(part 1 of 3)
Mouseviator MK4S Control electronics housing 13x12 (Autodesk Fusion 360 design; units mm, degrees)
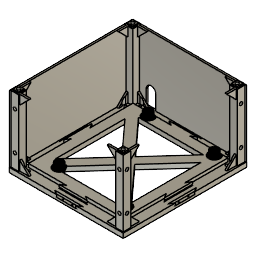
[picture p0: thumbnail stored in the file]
parameter "plate_width" = 130
parameter "plate_height" = 120
parameter "join_width1" = 10
parameter "join_width2" = 15
parameter "join_depth" = 3
parameter "plate_thick" = 5
parameter "plate_mount_square_side" = 7
parameter "locke_handle_height_1" = 8
parameter "lock_handle_chamfer_1" = 5
parameter "lock_handle_fillet_1" = 0.5
parameter "column_height" = 70
parameter "support_column_side" = 8
parameter "top_cover_thickness" = 3
parameter "wall_clearance" = 0.05
parameter "print_layer_height" = 0.2
parameter "side_wall_thick1" = 0.95 (= "( ( plate_square_thick - support_column_side ) / 2 ) - wall_clearance")
parameter "side_wall_thick2" = 1.95 (= "plate_square_thick - support_column_side - wall_clearance")
parameter "side_wall_length_L_inner" = 111.9 (= "plate_width - ( side_wall_col_length * 2 )")
parameter "side_wall_length_S_inner" = 101.9 (= "plate_height - ( side_wall_col_length * 2 )")
parameter "join_key_d" = 1.5 (= "join_depth / 2")
parameter "join_key_distance" = 5 (= "join_width1 / 2")
parameter "locke_handle_height_2" = 8
parameter "lock_handle_chamfer_2" = 5
parameter "lock_handle_fillet_2" = 0.5
parameter "locke_handle_height_3" = 8
parameter "lock_handle_chamfer_3" = 5
parameter "lock_handle_fillet_3" = 0.5
parameter "lock_column_clearance" = 0.075 (= "wall_clearance * 1.5")
parameter "psu_width" = 99
parameter "psu_height" = 82.5
parameter "psu_stand_height" = 5
parameter "joiner_spacing_1" = -0.05
parameter "joiner_spacing_2" = -0.05
parameter "joiner_spacing_2_1" = -0.05
parameter "joiner_spacing_2_2" = -0.05
parameter "joiner_spacing_3_1" = -0.05
parameter "plate_square_thick_1" = 10
parameter "column_lock_spacing_1" = 2
sketch "Sketch1" plane through (0, 0, 0) normal (0, 0, 1) x axis (1, 0, 0)
  line L1 (130.9644, 61.9879) -> (10.9644, 61.9879)
  line L2 (130.9644, -68.0121) -> (130.9644, 61.9879)
  line L3 (10.9644, -68.0121) -> (130.9644, -68.0121)
  line L4 (10.9644, 61.9879) -> (10.9644, -68.0121)
  line L5 (70.9644, -84.5025) -> (70.9644, 72)
  line L6 (146.0369, -3.0121) -> (3.7538, -3.0121)
  line L7 (120.9644, 51.9879) -> (20.9644, 51.9879)
  line L8 (120.9644, -58.0121) -> (120.9644, 51.9879)
  line L9 (20.9644, -58.0121) -> (120.9644, -58.0121)
  line L10 (20.9644, 51.9879) -> (20.9644, -58.0121)
  line L11 (20.9644, 61.9879) -> (10.9644, 61.9879)
  line L12 (20.9644, 51.9879) -> (20.9644, 61.9879)
  line L13 (10.9644, 51.9879) -> (20.9644, 51.9879)
  line L14 (10.9644, 61.9879) -> (10.9644, 51.9879)
  line L15 (120.9644, 61.9879) -> (130.9644, 61.9879)
  line L16 (120.9644, 51.9879) -> (120.9644, 61.9879)
  line L17 (130.9644, 51.9879) -> (120.9644, 51.9879)
  line L18 (130.9644, 61.9879) -> (130.9644, 51.9879)
  line L19 (120.9644, -68.0121) -> (130.9644, -68.0121)
  line L20 (120.9644, -58.0121) -> (120.9644, -68.0121)
  line L21 (130.9644, -58.0121) -> (120.9644, -58.0121)
  line L22 (130.9644, -68.0121) -> (130.9644, -58.0121)
  line L23 (20.9644, -68.0121) -> (10.9644, -68.0121)
  line L24 (20.9644, -58.0121) -> (20.9644, -68.0121)
  line L25 (10.9644, -58.0121) -> (20.9644, -58.0121)
  line L26 (10.9644, -68.0121) -> (10.9644, -58.0121)
  line L27 (122.9644, 59.9879) -> (128.9644, 59.9879)
  line L28 (122.9644, 53.9879) -> (122.9644, 59.9879)
  line L29 (128.9644, 53.9879) -> (122.9644, 53.9879)
  line L30 (128.9644, 59.9879) -> (128.9644, 53.9879)
  line L31 (18.9644, -66.0121) -> (12.9644, -66.0121)
  line L32 (18.9644, -60.0121) -> (18.9644, -66.0121)
  line L33 (12.9644, -60.0121) -> (18.9644, -60.0121)
  line L34 (12.9644, -66.0121) -> (12.9644, -60.0121)
  line L35 (18.9644, 59.9879) -> (12.9644, 59.9879)
  line L36 (18.9644, 53.9879) -> (18.9644, 59.9879)
  line L37 (12.9644, 53.9879) -> (18.9644, 53.9879)
  line L38 (12.9644, 59.9879) -> (12.9644, 53.9879)
  line L39 (122.9644, -66.0121) -> (128.9644, -66.0121)
  line L40 (122.9644, -60.0121) -> (122.9644, -66.0121)
  line L41 (128.9644, -60.0121) -> (122.9644, -60.0121)
  line L42 (128.9644, -66.0121) -> (128.9644, -60.0121)
  line L43 (60.9644, 51.9879) -> (70.9644, 51.9879)
  line L44 (80.9644, 51.9879) -> (70.9644, 51.9879)
  line L45 (70.9644, 54.9879) -> (70.9644, 51.9879)
  line L46 (85.9644, 54.9879) -> (70.9644, 54.9879)
  line L47 (55.9644, 54.9879) -> (70.9644, 54.9879)
  line L48 (55.9644, 54.9879) -> (60.9644, 51.9879)
  line L49 (80.9644, 51.9879) -> (85.9644, 54.9879)
  line L50 (111.4916, 56.9879) -> (2, 56.9879)
  line L51 (55.9644, 58.9879) -> (70.9644, 58.9879)
  line L52 (55.9644, 58.9879) -> (60.9644, 61.9879)
  line L53 (60.9644, 61.9879) -> (70.9644, 61.9879)
  line L54 (80.9644, 61.9879) -> (85.9644, 58.9879)
  line L55 (80.9644, 61.9879) -> (70.9644, 61.9879)
  line L56 (85.9644, 58.9879) -> (70.9644, 58.9879)
  line L57 (85.9644, -61.0121) -> (70.9644, -61.0121)
  line L58 (80.9644, -58.0121) -> (85.9644, -61.0121)
  line L59 (80.9644, -58.0121) -> (70.9644, -58.0121)
  line L60 (55.9644, -61.0121) -> (60.9644, -58.0121)
  line L61 (60.9644, -58.0121) -> (70.9644, -58.0121)
  line L62 (55.9644, -61.0121) -> (70.9644, -61.0121)
  line L63 (55.9644, -65.0121) -> (60.9644, -68.0121)
  line L64 (60.9644, -68.0121) -> (70.9644, -68.0121)
  line L65 (80.9644, -68.0121) -> (70.9644, -68.0121)
  line L66 (80.9644, -68.0121) -> (85.9644, -65.0121)
  line L67 (85.9644, -65.0121) -> (70.9644, -65.0121)
  line L68 (55.9644, -65.0121) -> (70.9644, -65.0121)
  line L69 (60.9644, 51.9879) -> (20.9644, 51.9879)
  line L70 (80.9644, 51.9879) -> (120.9644, 51.9879)
  line L71 (80.9644, -58.0121) -> (120.9644, -58.0121)
  line L72 (60.9644, -58.0121) -> (20.9644, -58.0121)
  line L73 (125.9644, -76) -> (125.9644, 65)
  line L74 (120.9644, 6.9879) -> (120.9644, -3.0121)
  line L75 (120.9644, -13.0121) -> (120.9644, -3.0121)
  line L76 (123.9644, -3.0121) -> (120.9644, -3.0121)
  line L77 (123.9644, 11.9879) -> (123.9644, -3.0121)
  line L78 (123.9644, -18.0121) -> (123.9644, -3.0121)
  line L79 (123.9644, 11.9879) -> (120.9644, 6.9879)
  line L80 (123.9644, -18.0121) -> (120.9644, -13.0121)
  line L81 (127.9644, -18.0121) -> (127.9644, -3.0121)
  line L82 (127.9644, -18.0121) -> (130.9644, -13.0121)
  line L83 (130.9644, -13.0121) -> (130.9644, -3.0121)
  line L84 (127.9644, 11.9879) -> (130.9644, 6.9879)
  line L85 (130.9644, 6.9879) -> (130.9644, -3.0121)
  line L86 (127.9644, 11.9879) -> (127.9644, -3.0121)
  line L87 (13.9644, 11.9879) -> (13.9644, -3.0121)
  line L88 (13.9644, -18.0121) -> (13.9644, -3.0121)
  line L89 (13.9644, -18.0121) -> (10.9644, -13.0121)
  line L90 (10.9644, -13.0121) -> (10.9644, -3.0121)
  line L91 (10.9644, 6.9879) -> (10.9644, -3.0121)
  line L92 (13.9644, 11.9879) -> (10.9644, 6.9879)
  line L93 (17.9644, 11.9879) -> (20.9644, 6.9879)
  line L94 (20.9644, 6.9879) -> (20.9644, -3.0121)
  line L95 (17.9644, 11.9879) -> (17.9644, -3.0121)
  line L96 (17.9644, -18.0121) -> (20.9644, -13.0121)
  line L97 (20.9644, -13.0121) -> (20.9644, -3.0121)
  line L98 (17.9644, -18.0121) -> (17.9644, -3.0121)
  line L99 (120.9644, 6.9879) -> (120.9644, 51.9879)
  line L100 (120.9644, -58.0121) -> (120.9644, -13.0121)
  line L101 (20.9644, -13.0121) -> (20.9644, -58.0121)
  line L102 (20.9644, 6.9879) -> (20.9644, 51.9879)
  line L103 (27.9644, 51.9879) -> (20.9644, 58.9879)
  line L104 (20.9644, 51.9879) -> (27.9644, 58.9879)
  line L105 (27.9644, 58.9879) -> (20.9644, 58.9879)
  line L106 (27.9644, 51.9879) -> (27.9644, 58.9879)
  line L107 (20.9644, 51.9879) -> (27.9644, 51.9879)
  line L108 (20.9644, 58.9879) -> (20.9644, 51.9879)
  line L109 (13.9644, 51.9879) -> (20.9644, 51.9879)
  line L110 (13.9644, 44.9879) -> (13.9644, 51.9879)
  line L111 (20.9644, 44.9879) -> (13.9644, 44.9879)
  line L112 (20.9644, 51.9879) -> (20.9644, 44.9879)
  line L113 (20.9644, 44.9879) -> (13.9644, 51.9879)
  line L114 (20.9644, 51.9879) -> (13.9644, 44.9879)
  line L115 (75, 60.4879) -> (35.7947, 60.4879)
  line L116 (12.4644, -21) -> (12.4644, 12.5586)
  line L117 (15.9644, -29) -> (15.9644, 22)
  circle C1 centre (24.4644, 55.4879) radius 1.5
  circle C2 centre (117.4644, 55.4879) radius 1.5
  circle C3 centre (24.4644, -61.5121) radius 1.5
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  point P38 (70.9644, 51.9879)
  point P49 (70.9644, 61.9879)
  point P39 (60.9644, 51.9879)
  point P48 (60.9644, 61.9879)
  point P40 (80.9644, 51.9879)
  point P51 (80.9644, 61.9879)
  point P41 (70.9644, 54.9879)
  point P46 (70.9644, 58.9879)
  point P42 (85.9644, 54.9879)
  point P50 (85.9644, 58.9879)
  point P43 (55.9644, 54.9879)
  point P47 (55.9644, 58.9879)
  point P55 (70.9644, -58.0121)
  point P56 (60.9644, -58.0121)
  point P54 (80.9644, -58.0121)
  point P52 (70.9644, -61.0121)
  point P53 (85.9644, -61.0121)
  point P57 (55.9644, -61.0121)
  point P63 (70.9644, -65.0121)
  point P59 (55.9644, -65.0121)
  point P58 (60.9644, -68.0121)
  point P60 (70.9644, -68.0121)
  point P62 (85.9644, -65.0121)
  point P61 (80.9644, -68.0121)
  point P66 (120.9644, -3.0121)
  point P75 (130.9644, -3.0121)
  point P67 (120.9644, 6.9879)
  point P76 (130.9644, 6.9879)
  point P68 (120.9644, -13.0121)
  point P74 (130.9644, -13.0121)
  point P69 (123.9644, -3.0121)
  point P72 (127.9644, -3.0121)
  point P70 (123.9644, 11.9879)
  point P77 (127.9644, 11.9879)
  point P71 (123.9644, -18.0121)
  point P73 (127.9644, -18.0121)
  point P86 (20.9644, -3.0121)
  point P84 (20.9644, 6.9879)
  point P88 (20.9644, -13.0121)
  point P87 (17.9644, -3.0121)
  point P85 (17.9644, 11.9879)
  point P89 (17.9644, -18.0121)
  point P78 (13.9644, -3.0121)
  point P80 (13.9644, -18.0121)
  point P81 (10.9644, -13.0121)
  point P82 (10.9644, -3.0121)
  point P83 (10.9644, 6.9879)
  point P79 (13.9644, 11.9879)
  point P93 (24.4644, 55.4879)
  point P102 (17.4644, 48.4879)
  point P108 (65.9644, 60.4879)
  point P118 (12.4644, 1.9879)
  point P2 (10.9644, 61.9879)
  point P3 (130.9644, 61.9879)
  point P5 (10.9644, -68.0121)
  point P95 (20.9644, 51.9879)
  point P99 (13.9644, 51.9879)
  point P101 (20.9644, 44.9879)
  horizontal L1
  vertical L2
  horizontal L3
  vertical L4
  perpendicular L3 L5
  horizontal L6
  horizontal L11
  vertical L12
  horizontal L13
  vertical L14
  horizontal L15
  vertical L16
  horizontal L17
  vertical L18
  horizontal L19
  vertical L20
  horizontal L21
  vertical L22
  horizontal L23
  vertical L24
  horizontal L25
  vertical L26
  midpoint L7 P38
  perpendicular L8 L43
  perpendicular L5 L44
  perpendicular L44 L45
  perpendicular L45 L46
  perpendicular L45 L47
  parallel L1 L50
  symmetric P38 L50 P49
  symmetric P39 L50 P48
  symmetric P40 L50 P51
  symmetric P41 L50 P46
  symmetric P42 L50 P50
  symmetric P43 L50 P47
  symmetric L6 P38 P55
  symmetric L6 P39 P56
  symmetric L6 P40 P54
  symmetric L6 P41 P52
  symmetric L6 P42 P53
  symmetric L6 P43 P57
  symmetric L6 P46 P63
  symmetric L6 P47 P59
  symmetric L6 P48 P58
  symmetric L6 P49 P60
  symmetric L6 P50 P62
  symmetric L6 P51 P61
  parallel L8 L73
  midpoint L8 P66
  perpendicular L6 L74
  perpendicular L6 L75
  perpendicular L74 L76
  perpendicular L76 L77
  perpendicular L76 L78
  symmetric L73 P66 P75
  symmetric L73 P67 P76
  symmetric L73 P68 P74
  symmetric L73 P69 P72
  symmetric L73 P70 P77
  symmetric L73 P71 P73
  symmetric L5 P66 P86
  symmetric L5 P67 P84
  symmetric L5 P68 P88
  symmetric L5 P69 P87
  symmetric L5 P70 P85
  symmetric L5 P71 P89
  symmetric L5 P72 P78
  symmetric L5 P73 P80
  symmetric L5 P74 P81
  symmetric L5 P75 P82
  symmetric L5 P76 P83
  symmetric L5 P77 P79
  midpoint L104 P93
  horizontal L105
  vertical L106
  horizontal L107
  vertical L108
  horizontal L109
  vertical L110
  horizontal L111
  vertical L112
  perpendicular L113 L114
  midpoint L114 P102
  perpendicular L5 L115
  coincident L115 P108
  parallel L4 L116
  coincident L116 P118
  parallel L116 L117
  dimension "d7" distance P2 P3 = 120 (= "plate_height")
  dimension "d8" distance P2 P5 = 130 (= "plate_width")
  dimension "d9" distance L4 L5 = 60 (= "plate_height / 2")
  dimension "d10" distance L1 L6 = 65 (= "plate_width / 2")
  dimension "plate_square_thick" = 10
  dimension "column_lock_spacing" = 2
  dimension "d14" distance P38 P39 = 10 (= "join_width1")
  dimension "d15" distance P38 P40 = 10 (= "join_width1")
  dimension "d16" distance P38 P41 = 3 (= "join_depth")
  dimension "d17" distance P41 P42 = 15 (= "join_width2")
  dimension "d18" distance P41 P43 = 15 (= "join_width2")
  dimension "d19" distance L1 L50 = 5 (= "plate_square_thick / 2")
  dimension "d20" distance L2 L73 = 5 (= "plate_square_thick / 2")
  dimension "d21" distance P66 P67 = 10 (= "join_width1")
  dimension "d22" distance P66 P68 = 10 (= "join_width1")
  dimension "d23" distance P66 P69 = 3
  dimension "d24" distance P69 P70 = 15 (= "join_width2")
  dimension "d25" distance P69 P71 = 15 (= "join_width2")
  dimension "plate_mount_hole_d" diameter C1 = 3
  dimension "d34" distance P95 P99 = 7 (= "plate_mount_square_side")
  dimension "d35" distance P95 P101 = 7 (= "plate_mount_square_side")
  dimension "d36" diameter = 3
  dimension "d245" distance L1 L115 = 1.5 (= "join_depth / 2")
  dimension "d246" diameter = 1.5 (= "join_key_d")
  dimension "d248" distance L5 P108 = 5 (= "join_key_distance")
  dimension "d250" distance L4 L116 = 1.5 (= "join_depth / 2")
  dimension "d251" diameter = 1.5
  dimension "d252" distance L6 P118 = 5 (= "join_key_distance")
  dimension "d253" distance L4 L117 = 5 (= "plate_square_thick / 2")
  dimension "d32" R-Pattern1-uDistance = 93 (= "plate_height - ( plate_square_thick * 2 ) - plate_mount_square_side")
  dimension "d33" R-Pattern1-vDistance = -117 (= "-( plate_width - ( plate_square_thick * 2 ) + ( plate_mount_square_side ) )")
  dimension "d39" R-Pattern2-uDistance = 106.5 (= "plate_height - plate_square_thick - ( plate_mount_square_side / 2 )")
  dimension "d40" R-Pattern2-vDistance = -103 (= "-( plate_width - ( plate_square_thick * 2 ) - plate_mount_square_side )")
  dimension "lock_handle_hole_d_1" diameter = 5
  dimension "lock_handle_hole_d_2" diameter = 5
  dimension "lock_handle_hole_d_2_1" diameter = 5
  dimension "lock_handle_hole_d_2_2" diameter = 5
  dimension "lock_handle_hole_d_3" diameter = 5
  dimension "plate_mount_hole_d_1" diameter = 3
  dimension "top_cover_cable_d" diameter = 10
extrude "Extrude1" new body sketch "Sketch1" along normal blind 5 (= "plate_thick")
sketch "Sketch2" plane through (0, 0, 5) normal (0, 0, 1) x axis (-1, 0, 0)
  line L1 (-128.9644, -53.9879) -> (-128.9644, -59.9879)
  line L2 (-122.9644, -53.9879) -> (-128.9644, -53.9879)
  line L3 (-122.9644, -59.9879) -> (-122.9644, -53.9879)
  line L4 (-128.9644, -59.9879) -> (-122.9644, -59.9879)
  line L5 (-12.9644, 60.0121) -> (-12.9644, 66.0121)
  line L6 (-18.9644, 60.0121) -> (-12.9644, 60.0121)
  line L7 (-18.9644, 66.0121) -> (-18.9644, 60.0121)
  line L8 (-12.9644, 66.0121) -> (-18.9644, 66.0121)
  line L9 (-60.9644, -51.9879) -> (-20.9644, -51.9879)
  line L10 (-55.9644, -54.9879) -> (-60.9644, -51.9879)
  line L11 (-85.9644, -54.9879) -> (-55.9644, -54.9879)
  line L12 (-80.9644, -51.9879) -> (-85.9644, -54.9879)
  line L13 (-120.9644, -51.9879) -> (-80.9644, -51.9879)
  line L14 (-120.9644, -6.9879) -> (-120.9644, -51.9879)
  line L15 (-123.9644, -11.9879) -> (-120.9644, -6.9879)
  line L16 (-123.9644, 18.0121) -> (-123.9644, -11.9879)
  line L17 (-120.9644, 13.0121) -> (-123.9644, 18.0121)
  line L18 (-120.9644, 58.0121) -> (-120.9644, 13.0121)
  line L19 (-80.9644, 58.0121) -> (-120.9644, 58.0121)
  line L20 (-85.9644, 61.0121) -> (-80.9644, 58.0121)
  line L21 (-55.9644, 61.0121) -> (-85.9644, 61.0121)
  line L22 (-60.9644, 58.0121) -> (-55.9644, 61.0121)
  line L23 (-20.9644, 58.0121) -> (-60.9644, 58.0121)
  line L24 (-20.9644, 13.0121) -> (-20.9644, 58.0121)
  line L25 (-17.9644, 18.0121) -> (-20.9644, 13.0121)
  line L26 (-17.9644, -11.9879) -> (-17.9644, 18.0121)
  line L27 (-20.9644, -6.9879) -> (-17.9644, -11.9879)
  line L28 (-20.9644, -51.9879) -> (-20.9644, -6.9879)
  line L29 (-12.9644, -53.9879) -> (-18.9644, -53.9879)
  line L30 (-12.9644, -59.9879) -> (-12.9644, -53.9879)
  line L31 (-18.9644, -59.9879) -> (-12.9644, -59.9879)
  line L32 (-18.9644, -53.9879) -> (-18.9644, -59.9879)
  line L33 (-128.9644, 60.0121) -> (-122.9644, 60.0121)
  line L34 (-128.9644, 66.0121) -> (-128.9644, 60.0121)
  line L35 (-122.9644, 66.0121) -> (-128.9644, 66.0121)
  line L36 (-122.9644, 60.0121) -> (-122.9644, 66.0121)
  line L37 (-10.9644, -6.9879) -> (-10.9644, -61.9879)
  line L38 (-13.9644, -11.9879) -> (-10.9644, -6.9879)
  line L39 (-13.9644, 18.0121) -> (-13.9644, -11.9879)
  line L40 (-10.9644, 13.0121) -> (-13.9644, 18.0121)
  line L41 (-10.9644, 68.0121) -> (-10.9644, 13.0121)
  line L42 (-60.9644, 68.0121) -> (-10.9644, 68.0121)
  line L43 (-55.9644, 65.0121) -> (-60.9644, 68.0121)
  line L44 (-85.9644, 65.0121) -> (-55.9644, 65.0121)
  line L45 (-80.9644, 68.0121) -> (-85.9644, 65.0121)
  line L46 (-130.9644, 68.0121) -> (-80.9644, 68.0121)
  line L47 (-130.9644, 13.0121) -> (-130.9644, 68.0121)
  line L48 (-127.9644, 18.0121) -> (-130.9644, 13.0121)
  line L49 (-127.9644, -11.9879) -> (-127.9644, 18.0121)
  line L50 (-130.9644, -6.9879) -> (-127.9644, -11.9879)
  line L51 (-130.9644, -61.9879) -> (-130.9644, -6.9879)
  line L52 (-80.9644, -61.9879) -> (-130.9644, -61.9879)
  line L53 (-85.9644, -58.9879) -> (-80.9644, -61.9879)
  line L54 (-55.9644, -58.9879) -> (-85.9644, -58.9879)
  line L55 (-60.9644, -61.9879) -> (-55.9644, -58.9879)
  line L56 (-10.9644, -61.9879) -> (-60.9644, -61.9879)
  circle C1 centre (-17.4644, -48.4879) radius 1.5
  circle C2 centre (-123.9644, -48.4879) radius 1.5
  circle C3 centre (-117.4644, -55.4879) radius 1.5
  circle C4 centre (-24.4644, -55.4879) radius 1.5
  circle C5 centre (-24.4644, 61.5121) radius 1.5
  circle C6 centre (-17.4644, 54.5121) radius 1.5
  circle C7 centre (-123.9644, 54.5121) radius 1.5
  circle C8 centre (-117.4644, 61.5121) radius 1.5
hole "Hole1" HoleDepth 18 HoleDiameter 3.4 TipAngle 118
sketch "Sketch1" plane through (0, 0, 0) normal (0, 0, 1) x axis (1, 0, 0)
  line L1 (-15, -9) -> (-15, 21)
  line L2 (-7, 6) -> (-28, 6)
  line L3 (-18, 16) -> (-18, 6)
  line L4 (-18, -4) -> (-18, 6)
  line L5 (-15, 21) -> (-18, 16)
  line L6 (-15, -9) -> (-18, -4)
  line L7 (-21, -9) -> (-18, -4)
  line L8 (-18, -4) -> (-18, 6)
  line L9 (-18, 16) -> (-18, 6)
  line L10 (-21, 21) -> (-18, 16)
  line L11 (-21, -9) -> (-21, 21)
  line L12 (-15.05, 20.8195) -> (-18, 15.9028)
  line L13 (-15.05, -8.8195) -> (-15.05, 20.8195)
  line L14 (-15.05, -8.8195) -> (-18, -3.9028)
  line L15 (-20.95, -8.8195) -> (-18, -3.9028)
  line L16 (-20.95, -8.8195) -> (-20.95, 20.8195)
  line L17 (-20.95, 20.8195) -> (-18, 15.9028)
  line L18 (-16.5, -15) -> (-16.5, 22.7414)
  circle C1 centre (-16.5, 11) radius 0.75
  circle C2 centre (-16.5, 11) radius 0.7
  circle C3 centre (-16.5, 1) radius 0.7
  circle C4 centre (-19.5, 11) radius 0.7
  circle C5 centre (-19.5, 1) radius 0.7
  point P2 (-15, 21)
  point P13 (-21, 21)
  point P3 (-15, -9)
  point P10 (-21, -9)
  point P6 (-18, 6)
  point P11 (-18, 6)
  point P7 (-18, 16)
  point P12 (-18, 16)
  point P8 (-18, -4)
  point P9 (-18, -4)
  point P22 (-16.5, 11)
  vertical L1
  horizontal L2
  perpendicular L2 L3
  perpendicular L2 L4
  symmetric P2 L3 P13
  symmetric P3 L3 P10
  symmetric P6 L3 P11
  symmetric P7 L3 P12
  symmetric L3 P8 P9
  parallel L1 L18
  coincident L18 P22
  symmetric L2 C2 C3
  symmetric L4 C2 C4
  symmetric L4 C3 C5
  dimension "d49" distance P6 P7 = 10 (= "join_width1")
  dimension "d50" distance P6 P8 = 10 (= "join_width1")
  dimension "d51" distance P2 P3 = 30 (= "join_width2 * 2")
  dimension "d52" distance L1 L3 = 3 (= "join_depth")
  dimension "joiner_spacing" = -0.05
  dimension "d256" distance L9 L18 = 1.5 (= "join_depth / 2")
  dimension "d257" diameter C1 = 1.5 (= "join_key_d")
  dimension "d258" distance L2 P22 = 5 (= "join_key_distance")
extrude "Extrude1" new body sketch "Sketch1" profile of L13 L12 L15 L14 L16 L17 along normal blind 5 (= "plate_thick")
sketch "Sketch2" plane through (0, 0, 5) normal (0, 0, 1) x axis (-1, 0, 0)
  line L1 (18, -15.9028) -> (15.05, -20.8195)
  line L2 (20.95, -20.8195) -> (18, -15.9028)
  line L3 (20.95, 8.8195) -> (20.95, -20.8195)
  line L4 (18, 3.9028) -> (20.95, 8.8195)
  line L5 (15.05, 8.8195) -> (18, 3.9028)
  line L6 (15.05, -20.8195) -> (15.05, 8.8195)
  line L7 (18, -16) -> (18, -6)
  line L8 (18, 4) -> (18, -6)
  line L9 (17, 3.9028) -> (17, -15.9028)
  line L10 (18, 3.9028) -> (17, 3.9028)
  line L11 (19, 3.9028) -> (19, -15.9028)
  line L12 (18, 3.9028) -> (19, 3.9028)
  line L13 (19, -15.9028) -> (18, -15.9028)
  line L14 (17, -15.9028) -> (18, -15.9028)
  point P6 (18, 3.9028)
  point P14 (18, 3.9028)
  point P3 (18, -15.9028)
  point P15 (18, -15.9028)
  vertical L9
  horizontal L10
  vertical L11
  horizontal L12
  coincident P6 P14
  coincident P3 P15
  perpendicular L11 L13
  perpendicular L9 L14
extrude "Extrude2" add sketch "Sketch2" profile of L1 L2 L4 L5 L7 L8 L9 L10 L11 L12 along normal blind 8 named "locke_handle_height"
chamfer "Chamfer1" distance 5 named "lock_handle_chamfer"
sketch "Sketch3" plane through (-19, 0, 0) normal (-1, 0, 0) x axis (0, -1, 0)
  line L1 (-1.0972, 13) -> (3.9028, 8)
  line L2 (-10.9028, 13) -> (-1.0972, 13)
  line L3 (-15.9028, 8) -> (-10.9028, 13)
  line L4 (-15.9028, 5) -> (-15.9028, 8)
  line L5 (3.9028, 5) -> (-15.9028, 5)
  line L6 (3.9028, 8) -> (3.9028, 5)
  line L7 (-6, 14.247) -> (-6, 5)
  line L8 (4.7349, 8.2) -> (-17.4775, 8.2)
  line L9 (3.9028, 5) -> (-15.9028, 5)
  circle C1 centre (-10, 8.2) radius 2.5
  circle C2 centre (-2, 8.2) radius 2.5
  point P8 (-6, 5)
  point P14 (-10, 8.2)
  midpoint L5 P8
  perpendicular L2 L7
  perpendicular L7 L8
  coincident L8 P14
  symmetric L7 C1 C2
  dimension "d59" distance L8 L9 = 3.2 (= "locke_handle_height * 0.4")
  dimension "lock_handle_hole_d" diameter C1 = 5
  dimension "d61" distance L7 P14 = 4 (= "join_width1 * 0.40")
extrude "Extrude3" cut sketch "Sketch3" profile of C1 C2 no distance stored
fillet "Fillet1" radius 0.5 named "lock_handle_fillet"
fillet "Fillet2" radius 0.5 (= "lock_handle_fillet")
sketch "base" plane through (0, 0, 0) normal (0, 0, 1) x axis (1, 0, 0)
  line L1 (12.9644, 53.9879) -> (18.9644, 53.9879)
  line L2 (12.9644, 59.9879) -> (12.9644, 53.9879)
  line L3 (18.9644, 59.9879) -> (12.9644, 59.9879)
  line L4 (18.9644, 53.9879) -> (18.9644, 59.9879)
  line L5 (13.0144, 54.0379) -> (18.9144, 54.0379)
  line L6 (13.0144, 59.9379) -> (13.0144, 54.0379)
  line L7 (18.9144, 59.9379) -> (13.0144, 59.9379)
  line L8 (18.9144, 54.0379) -> (18.9144, 59.9379)
  line L9 (11.9644, 52.9879) -> (19.9644, 52.9879)
  line L10 (11.9644, 60.9879) -> (11.9644, 52.9879)
  line L11 (19.9644, 60.9879) -> (11.9644, 60.9879)
  line L12 (19.9644, 52.9879) -> (19.9644, 60.9879)
  dimension "d67" = 0.05
  dimension "d68" = -1
extrude "Extrude2" new body sketch "base" profile of L1 L2 L3 L4 L9 L10 L11 L12 blind 70 (= "column_height") from offset 5 (= "plate_thick")
extrude "Extrude3" add sketch "Sketch1" profile of L36 L35 L38 L37 along normal blind 75 (= "plate_thick + column_height")
sketch "supports bottom" plane through (0, 0, 5) normal (0, 0, 1) x axis (-1, 0, 0)
  line L1 (-128.9644, -53.9879) -> (-128.9644, -59.9879)
  line L2 (-122.9644, -53.9879) -> (-128.9644, -53.9879)
  line L3 (-122.9644, -59.9879) -> (-122.9644, -53.9879)
  line L4 (-128.9644, -59.9879) -> (-122.9644, -59.9879)
  line L5 (-12.9644, 60.0121) -> (-12.9644, 66.0121)
  line L6 (-18.9644, 60.0121) -> (-12.9644, 60.0121)
  line L7 (-18.9644, 66.0121) -> (-18.9644, 60.0121)
  line L8 (-12.9644, 66.0121) -> (-18.9644, 66.0121)
  line L9 (-60.9644, -51.9879) -> (-20.9644, -51.9879)
  line L10 (-55.9644, -54.9879) -> (-60.9644, -51.9879)
  line L11 (-85.9644, -54.9879) -> (-55.9644, -54.9879)
  line L12 (-80.9644, -51.9879) -> (-85.9644, -54.9879)
  line L13 (-120.9644, -51.9879) -> (-80.9644, -51.9879)
  line L14 (-120.9644, -6.9879) -> (-120.9644, -51.9879)
  line L15 (-123.9644, -11.9879) -> (-120.9644, -6.9879)
  line L16 (-123.9644, 18.0121) -> (-123.9644, -11.9879)
  line L17 (-120.9644, 13.0121) -> (-123.9644, 18.0121)
  line L18 (-120.9644, 58.0121) -> (-120.9644, 13.0121)
  line L19 (-80.9644, 58.0121) -> (-120.9644, 58.0121)
  line L20 (-85.9644, 61.0121) -> (-80.9644, 58.0121)
  line L21 (-55.9644, 61.0121) -> (-85.9644, 61.0121)
  line L22 (-60.9644, 58.0121) -> (-55.9644, 61.0121)
  line L23 (-20.9644, 58.0121) -> (-60.9644, 58.0121)
  line L24 (-20.9644, 13.0121) -> (-20.9644, 58.0121)
  line L25 (-17.9644, 18.0121) -> (-20.9644, 13.0121)
  line L26 (-17.9644, -11.9879) -> (-17.9644, 18.0121)
  line L27 (-20.9644, -6.9879) -> (-17.9644, -11.9879)
  line L28 (-20.9644, -51.9879) -> (-20.9644, -6.9879)
  line L29 (-12.9644, -53.9879) -> (-18.9644, -53.9879)
  line L30 (-12.9644, -59.9879) -> (-12.9644, -53.9879)
  line L31 (-18.9644, -59.9879) -> (-12.9644, -59.9879)
  line L32 (-18.9644, -53.9879) -> (-18.9644, -59.9879)
  line L33 (-128.9644, 60.0121) -> (-122.9644, 60.0121)
  line L34 (-128.9644, 66.0121) -> (-128.9644, 60.0121)
  line L35 (-122.9644, 66.0121) -> (-128.9644, 66.0121)
  line L36 (-122.9644, 60.0121) -> (-122.9644, 66.0121)
  line L37 (-10.9644, -6.9879) -> (-10.9644, -61.9879)
  line L38 (-13.9644, -11.9879) -> (-10.9644, -6.9879)
  line L39 (-13.9644, 18.0121) -> (-13.9644, -11.9879)
  line L40 (-10.9644, 13.0121) -> (-13.9644, 18.0121)
  line L41 (-10.9644, 68.0121) -> (-10.9644, 13.0121)
  line L42 (-60.9644, 68.0121) -> (-10.9644, 68.0121)
  line L43 (-55.9644, 65.0121) -> (-60.9644, 68.0121)
  line L44 (-85.9644, 65.0121) -> (-55.9644, 65.0121)
  line L45 (-80.9644, 68.0121) -> (-85.9644, 65.0121)
  line L46 (-130.9644, 68.0121) -> (-80.9644, 68.0121)
  line L47 (-130.9644, 13.0121) -> (-130.9644, 68.0121)
  line L48 (-127.9644, 18.0121) -> (-130.9644, 13.0121)
  line L49 (-127.9644, -11.9879) -> (-127.9644, 18.0121)
  line L50 (-130.9644, -6.9879) -> (-127.9644, -11.9879)
  line L51 (-130.9644, -61.9879) -> (-130.9644, -6.9879)
  line L52 (-80.9644, -61.9879) -> (-130.9644, -61.9879)
  line L53 (-85.9644, -58.9879) -> (-80.9644, -61.9879)
  line L54 (-55.9644, -58.9879) -> (-85.9644, -58.9879)
  line L55 (-60.9644, -61.9879) -> (-55.9644, -58.9879)
  line L56 (-10.9644, -61.9879) -> (-60.9644, -61.9879)
  line L57 (-11.9644, -52.9879) -> (-19.9644, -52.9879)
  line L58 (-11.9644, -60.9879) -> (-11.9644, -52.9879)
  line L59 (-19.9644, -60.9879) -> (-11.9644, -60.9879)
  line L60 (-19.9644, -52.9879) -> (-19.9644, -60.9879)
  line L61 (-14.9644, -52.9879) -> (-12.9644, -52.9879)
  line L62 (-14.9644, -42.9879) -> (-14.9644, -52.9879)
  line L63 (-12.9644, -42.9879) -> (-14.9644, -42.9879)
  line L64 (-12.9644, -52.9879) -> (-12.9644, -42.9879)
  line L65 (-29.9644, -59.9879) -> (-19.9644, -59.9879)
  line L66 (-29.9644, -57.9879) -> (-29.9644, -59.9879)
  line L67 (-19.9644, -57.9879) -> (-29.9644, -57.9879)
  line L68 (-19.9644, -59.9879) -> (-19.9644, -57.9879)
  circle C1 centre (-24.4644, 61.5121) radius 1.7
  circle C2 centre (-123.9644, 54.5121) radius 1.7
  circle C3 centre (-117.4644, -55.4879) radius 1.7
  circle C4 centre (-17.4644, -48.4879) radius 1.7
  circle C5 centre (-24.4644, -55.4879) radius 1.7
  circle C6 centre (-123.9644, -48.4879) radius 1.7
  circle C7 centre (-117.4644, 61.5121) radius 1.7
  circle C8 centre (-17.4644, 54.5121) radius 1.7
  circle C9 centre (-17.4644, -48.4879) radius 1.7
  circle C10 centre (-24.4644, -55.4879) radius 1.7
  circle C11 centre (-17.4644, -48.4879) radius 3.15
  circle C12 centre (-24.4644, -55.4879) radius 3.15
  point P70 (-12.9644, -52.9879)
  point P74 (-19.9644, -59.9879)
  point P71 (-14.9644, -52.9879)
  point P73 (-12.9644, -42.9879)
  point P75 (-29.9644, -59.9879)
  point P77 (-19.9644, -57.9879)
  horizontal L61
  vertical L62
  horizontal L63
  vertical L64
  coincident L57 P70
  horizontal L65
  vertical L66
  horizontal L67
  vertical L68
  coincident L60 P74
  concentric C9 C11
  concentric C10 C12
  dimension "column_support_width" distance P70 P71 = 2
  dimension "column_support_height" distance P70 P73 = 10
  dimension "d79" distance P74 P75 = 10 (= "column_support_height")
  dimension "d80" distance P74 P77 = 2 (= "column_support_width")
  dimension "M3_head_d" diameter C11 = 6.3
  dimension "d85" diameter C12 = 6.3 (= "M3_head_d")
extrude "Extrude5" add sketch "supports bottom" profile of L53 L57 L60 L61 L62 L63 L64 L65 L66 L67 L68 C11 C12 along normal blind 10 (= "column_support_height")
chamfer "Chamfer2" distance 10 (= "column_support_height")
sketch "left side holes" plane through (0, 0, 75) normal (0, 0, 1) x axis (-1, 0, 0)
  line L1 (-11.9644, -60.9879) -> (-19.9644, -60.9879)
  line L2 (-11.9644, -52.9879) -> (-11.9644, -60.9879)
  line L3 (-19.9644, -52.9879) -> (-11.9644, -52.9879)
  line L4 (-19.9644, -60.9879) -> (-19.9644, -52.9879)
  line L5 (-19.9644, -57.9879) -> (-29.9644, -57.9879)
  line L6 (-19.9644, -59.9879) -> (-19.9644, -57.9879)
  line L7 (-29.9644, -59.9879) -> (-19.9644, -59.9879)
  line L8 (-29.9644, -57.9879) -> (-29.9644, -59.9879)
  line L9 (-14.9644, -42.9879) -> (-14.9644, -52.9879)
  line L10 (-12.9644, -42.9879) -> (-14.9644, -42.9879)
  line L11 (-14.9644, -52.9879) -> (-12.9644, -52.9879)
  line L12 (-12.9644, -52.9879) -> (-12.9644, -42.9879)
  line L13 (-18.9144, -59.9379) -> (-13.0144, -59.9379)
  line L14 (-18.9144, -54.0379) -> (-18.9144, -59.9379)
  line L15 (-13.0144, -54.0379) -> (-18.9144, -54.0379)
  line L16 (-13.0144, -59.9379) -> (-13.0144, -54.0379)
  line L17 (-18.9644, -59.9879) -> (-12.9644, -59.9879)
  line L18 (-18.9644, -53.9879) -> (-18.9644, -59.9879)
  line L19 (-12.9644, -53.9879) -> (-18.9644, -53.9879)
  line L20 (-12.9644, -59.9879) -> (-12.9644, -53.9879)
  circle C1 centre (-15.9644, -56.9879) radius 1.7
  dimension "M3_d" diameter C1 = 3.4
extrude "Extrude6" add sketch "left side holes" profile of L3 L4 L5 L6 L7 L8 L9 L10 L11 L12 no distance stored
chamfer "Chamfer3" distance 10 (= "column_support_height")
hole "Hole1" HoleDepth 10 (= "column_support_height") HoleDiameter 3.4 TipAngle 118
sketch "Sketch2" plane through (11.9644, 0, 0) normal (-1, 0, 0) x axis (0, -1, 0)
  line L1 (-52.9879, 5) -> (-60.9879, 5)
  line L2 (-52.9879, 75) -> (-52.9879, 5)
  line L3 (-60.9879, 75) -> (-52.9879, 75)
  line L4 (-60.9879, 5) -> (-60.9879, 75)
  line L5 (-44, 60) -> (-67, 60)
  line L6 (-48, 20) -> (-69, 20)
  circle C1 centre (-56.9879, 60) radius 1.7
  circle C2 centre (-56.9879, 20) radius 1.7
  point P14 (-56.9879, 60)
  point P15 (-56.9879, 20)
  point P5 (-60.9879, 75)
  point P2 (-60.9879, 5)
  perpendicular L2 L5
  perpendicular L2 L6
  coincident L5 P14
  coincident L6 P15
  dimension "d96" distance P5 L5 = 15 (= "column_support_height * 1.5")
  dimension "d97" distance P2 L6 = 15 (= "column_support_height * 1.5")
  dimension "d98" diameter C1 = 3.4 (= "M3_d")
  dimension "d100" distance L4 P14 = 4 (= "support_column_side / 2")
  dimension "d101" diameter C2 = 3.4 (= "M3_d")
  dimension "d102" distance L4 P15 = 4 (= "support_column_side / 2")
sketch "Sketch4" plane through (0, 60.9879, 0) normal (0, 1, 0) x axis (-1, 0, 0)
  line L1 (-11.9644, 5) -> (-19.9644, 5)
  line L2 (-11.9644, 75) -> (-11.9644, 5)
  line L3 (-19.9644, 75) -> (-11.9644, 75)
  line L4 (-19.9644, 5) -> (-19.9644, 75)
  line L5 (-23.511, 60) -> (-11.9644, 60)
  line L6 (-25, 20) -> (-11.9644, 20)
  circle C1 centre (-15.9644, 60) radius 1.7
  circle C2 centre (-15.9644, 20) radius 1.7
  point P7 (-11.9644, 60)
  point P8 (-11.9644, 60)
  point P6 (-11.9644, 20)
  point P10 (-11.9644, 20)
  point P12 (-15.9644, 60)
  point P13 (-15.9644, 20)
  coincident P7 P8
  perpendicular L4 L5
  coincident P6 P10
  perpendicular L2 L6
  coincident L5 P12
  coincident L6 P13
  dimension "d103" diameter C1 = 3.4 (= "M3_d")
  dimension "d104" diameter C2 = 3.4 (= "M3_d")
  dimension "d105" distance L2 P12 = 4 (= "support_column_side / 2")
  dimension "d106" distance L2 P13 = 4 (= "support_column_side / 2")
hole "Hole2" HoleDepth 5.76 (= "support_column_side * 0.72") HoleDiameter 3.4 TipAngle 180
hole "Hole3" HoleDepth 5.76 (= "support_column_side * 0.72") HoleDiameter 3.4 TipAngle 180
copy_paste "CopyPaste1"
copy_paste "CopyPaste2"
copy_paste "CopyPaste3"
position "Position2"
sketch "base" plane through (0, 0, 75) normal (0, 0, 1) x axis (-1, 0, 0)
  line L1 (-10.9644, -61.9879) -> (-10.9644, 68.0121)
  line L2 (-130.9644, -61.9879) -> (-10.9644, -61.9879)
  line L3 (-130.9644, 68.0121) -> (-130.9644, -61.9879)
  line L4 (-10.9644, 68.0121) -> (-130.9644, 68.0121)
  line L5 (-20.9644, -51.9879) -> (-20.9644, 58.0121)
  line L6 (-120.9644, -51.9879) -> (-20.9644, -51.9879)
  line L7 (-120.9644, 58.0121) -> (-120.9644, -51.9879)
  line L8 (-20.9644, 58.0121) -> (-120.9644, 58.0121)
  line L9 (-18.9644, -59.9879) -> (-12.9644, -59.9879)
  line L10 (-18.9644, -53.9879) -> (-18.9644, -59.9879)
  line L11 (-12.9644, -59.9879) -> (-12.9644, -53.9879)
  line L12 (-12.9644, -53.9879) -> (-18.9644, -53.9879)
  line L13 (-122.9644, -59.9879) -> (-122.9644, -53.9879)
  line L14 (-128.9644, -59.9879) -> (-122.9644, -59.9879)
  line L15 (-128.9644, -53.9879) -> (-128.9644, -59.9879)
  line L16 (-122.9644, -53.9879) -> (-128.9644, -53.9879)
  line L17 (-12.9644, 60.0121) -> (-12.9644, 66.0121)
  line L18 (-18.9644, 60.0121) -> (-12.9644, 60.0121)
  line L19 (-18.9644, 66.0121) -> (-18.9644, 60.0121)
  line L20 (-12.9644, 66.0121) -> (-18.9644, 66.0121)
  line L21 (-122.9644, 60.0121) -> (-122.9644, 66.0121)
  line L22 (-128.9644, 60.0121) -> (-122.9644, 60.0121)
  line L23 (-128.9644, 66.0121) -> (-128.9644, 60.0121)
  line L24 (-122.9644, 66.0121) -> (-128.9644, 66.0121)
  line L25 (-55.9644, -58.9879) -> (-70.9644, -58.9879)
  line L26 (-55.9644, -58.9879) -> (-60.9644, -61.9879)
  line L27 (-85.9644, -58.9879) -> (-85.9644, -58.9879)
  line L28 (-80.9644, -61.9879) -> (-85.9644, -58.9879)
  line L29 (-13.9644, -11.9879) -> (-10.9644, -6.9879)
  line L30 (-13.9644, -11.9879) -> (-13.9644, 3.0121)
  line L31 (-13.9644, 18.0121) -> (-13.9644, 3.0121)
  line L32 (-13.9644, 18.0121) -> (-10.9644, 13.0121)
  line L33 (-127.9644, -11.9879) -> (-130.9644, -6.9879)
  line L34 (-127.9644, -11.9879) -> (-127.9644, 3.0121)
  line L35 (-127.9644, 18.0121) -> (-127.9644, 3.0121)
  line L36 (-127.9644, 18.0121) -> (-130.9644, 13.0121)
  line L37 (-80.9644, 68.0121) -> (-85.9644, 65.0121)
  line L38 (-85.9644, 65.0121) -> (-70.9644, 65.0121)
  line L39 (-55.9644, 65.0121) -> (-70.9644, 65.0121)
  line L40 (-55.9644, 65.0121) -> (-60.9644, 68.0121)
  circle C1 centre (-75.9644, -60.4879) radius 0.75
  circle C2 centre (-65.9644, -60.4879) radius 0.75
  circle C3 centre (-12.4644, 8.0121) radius 0.75
  circle C4 centre (-12.4644, -1.9879) radius 0.75
  circle C5 centre (-129.4644, -1.9879) radius 0.75
  circle C6 centre (-129.4644, 8.0121) radius 0.75
  circle C7 centre (-75.9644, 66.5121) radius 0.75
  circle C8 centre (-65.9644, 66.5121) radius 0.75
  dimension "d121" = 10 (= "plate_square_thick")
  dimension "d241" R-Pattern1-vDistance = 120 (= "plate_width - plate_square_thick")
extrude "Extrude1" new body sketch "base" profile of L1 L2 L3 L4 L5 L6 L7 L8 L9 L10 L11 L12 L13 L14 L15 L16 L17 L18 L19 L20 L21 L22 L23 L24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 along normal blind 3 (= "top_cover_thickness")
sketch "mount holes" plane through (0, 0, 78) normal (0, 0, 1) x axis (-1, 0, 0)
  line L1 (-130.9644, -61.9879) -> (-130.9644, 68.0121)
  line L2 (-10.9644, -61.9879) -> (-130.9644, -61.9879)
  line L3 (-10.9644, 68.0121) -> (-10.9644, -61.9879)
  line L4 (-130.9644, 68.0121) -> (-10.9644, 68.0121)
  circle C1 centre (-15.9644, -56.9879) radius 1.7
  circle C2 centre (-125.9644, -56.9879) radius 1.7
  circle C3 centre (-15.9644, 63.0121) radius 1.7
  circle C4 centre (-125.9644, 63.0121) radius 1.7
  dimension "d163" R-Pattern1-vDistance = 120 (= "plate_width - plate_square_thick")
hole "Hole1" HoleDepth 4 HoleDiameter 3.4 TipAngle 118 CSDiameter 6.3 CSAngle 90
sketch "wall_base" plane through (0, 0, 5) normal (0, 0, 1) x axis (-1, 0, 0)
  line L1 (-128.9644, -53.9879) -> (-128.9644, -59.9879)
  line L2 (-122.9644, -53.9879) -> (-128.9644, -53.9879)
  line L3 (-122.9644, -59.9879) -> (-122.9644, -53.9879)
  line L4 (-128.9644, -59.9879) -> (-122.9644, -59.9879)
  line L5 (-12.9644, 60.0121) -> (-12.9644, 66.0121)
  line L6 (-18.9644, 60.0121) -> (-12.9644, 60.0121)
  line L7 (-18.9644, 66.0121) -> (-18.9644, 60.0121)
  line L8 (-12.9644, 66.0121) -> (-18.9644, 66.0121)
  line L9 (-60.9644, -51.9879) -> (-20.9644, -51.9879)
  line L10 (-55.9644, -54.9879) -> (-60.9644, -51.9879)
  line L11 (-85.9644, -54.9879) -> (-55.9644, -54.9879)
  line L12 (-80.9644, -51.9879) -> (-85.9644, -54.9879)
  line L13 (-120.9644, -51.9879) -> (-80.9644, -51.9879)
  line L14 (-120.9644, -6.9879) -> (-120.9644, -51.9879)
  line L15 (-123.9644, -11.9879) -> (-120.9644, -6.9879)
  line L16 (-123.9644, 18.0121) -> (-123.9644, -11.9879)
  line L17 (-120.9644, 13.0121) -> (-123.9644, 18.0121)
  line L18 (-120.9644, 58.0121) -> (-120.9644, 13.0121)
  line L19 (-80.9644, 58.0121) -> (-120.9644, 58.0121)
  line L20 (-85.9644, 61.0121) -> (-80.9644, 58.0121)
  line L21 (-55.9644, 61.0121) -> (-85.9644, 61.0121)
  line L22 (-60.9644, 58.0121) -> (-55.9644, 61.0121)
  line L23 (-20.9644, 58.0121) -> (-60.9644, 58.0121)
  line L24 (-20.9644, 13.0121) -> (-20.9644, 58.0121)
  line L25 (-17.9644, 18.0121) -> (-20.9644, 13.0121)
  line L26 (-17.9644, -11.9879) -> (-17.9644, 18.0121)
  line L27 (-20.9644, -6.9879) -> (-17.9644, -11.9879)
  line L28 (-20.9644, -51.9879) -> (-20.9644, -6.9879)
  line L29 (-12.9644, -53.9879) -> (-18.9644, -53.9879)
  line L30 (-12.9644, -59.9879) -> (-12.9644, -53.9879)
  line L31 (-18.9644, -59.9879) -> (-12.9644, -59.9879)
  line L32 (-18.9644, -53.9879) -> (-18.9644, -59.9879)
  line L33 (-128.9644, 60.0121) -> (-122.9644, 60.0121)
  line L34 (-128.9644, 66.0121) -> (-128.9644, 60.0121)
  line L35 (-122.9644, 66.0121) -> (-128.9644, 66.0121)
  line L36 (-122.9644, 60.0121) -> (-122.9644, 66.0121)
  line L37 (-10.9644, -6.9879) -> (-10.9644, -61.9879)
  line L38 (-13.9644, -11.9879) -> (-10.9644, -6.9879)
  line L39 (-13.9644, 18.0121) -> (-13.9644, -11.9879)
  line L40 (-10.9644, 13.0121) -> (-13.9644, 18.0121)
  line L41 (-10.9644, 68.0121) -> (-10.9644, 13.0121)
  line L42 (-60.9644, 68.0121) -> (-10.9644, 68.0121)
  line L43 (-55.9644, 65.0121) -> (-60.9644, 68.0121)
  line L44 (-85.9644, 65.0121) -> (-55.9644, 65.0121)
  line L45 (-80.9644, 68.0121) -> (-85.9644, 65.0121)
  line L46 (-130.9644, 68.0121) -> (-80.9644, 68.0121)
  line L47 (-130.9644, 13.0121) -> (-130.9644, 68.0121)
  line L48 (-127.9644, 18.0121) -> (-130.9644, 13.0121)
  line L49 (-127.9644, -11.9879) -> (-127.9644, 18.0121)
  line L50 (-130.9644, -6.9879) -> (-127.9644, -11.9879)
  line L51 (-130.9644, -61.9879) -> (-130.9644, -6.9879)
  line L52 (-80.9644, -61.9879) -> (-130.9644, -61.9879)
  line L53 (-85.9644, -58.9879) -> (-80.9644, -61.9879)
  line L54 (-55.9644, -58.9879) -> (-85.9644, -58.9879)
  line L55 (-60.9644, -61.9879) -> (-55.9644, -58.9879)
  line L56 (-10.9644, -61.9879) -> (-60.9644, -61.9879)
  line L57 (-130.9644, -61.9879) -> (-130.9644, 68.0121)
  line L58 (-130.9644, -61.9172) -> (-130.0144, -60.9672)
  line L59 (-130.0144, -52.9379) -> (-130.0144, -60.9672)
  line L60 (-129.0144, -52.9379) -> (-130.0144, -52.9379)
  line L61 (-129.0144, 58.9451) -> (-129.0144, -52.9379)
  line L62 (-130.0144, 58.9621) -> (-129.0144, 58.9451)
  line L63 (-130.0144, 66.9914) -> (-130.0144, 58.9621)
  line L64 (-130.9644, 67.9414) -> (-130.0144, 66.9914)
  line L65 (-129.9644, -52.9879) -> (-129.9644, -60.9879)
  line L66 (-128.9644, -52.9879) -> (-129.9644, -52.9879)
  line L67 (-128.9644, 58.9942) -> (-128.9644, -52.9879)
  line L68 (-129.9644, 59.0113) -> (-128.9644, 58.9942)
  line L69 (-129.9644, 67.0121) -> (-129.9644, 59.0113)
  line L70 (-130.9644, -61.9879) -> (-129.9644, -60.9879)
  line L71 (-130.9644, 68.0121) -> (-129.9644, 67.0121)
  circle C1 centre (-24.4644, 61.5121) radius 1.7
  circle C2 centre (-123.9644, 54.5121) radius 1.7
  circle C3 centre (-117.4644, -55.4879) radius 1.7
  circle C4 centre (-17.4644, -48.4879) radius 1.7
  circle C5 centre (-24.4644, -55.4879) radius 1.7
  circle C6 centre (-123.9644, -48.4879) radius 1.7
  circle C7 centre (-117.4644, 61.5121) radius 1.7
  circle C8 centre (-17.4644, 54.5121) radius 1.7
  point P69 (-130.9644, 68.0121)
  point P74 (-130.9644, 68.0121)
  point P68 (-130.9644, -61.9879)
  point P75 (-130.9644, -61.9879)
  point P82 (-130.9644, 67.9414)
  point P83 (-130.9644, -61.9172)
  point P90 (-130.9644, -61.9879)
  point P91 (-130.9644, 68.0121)
  point P77 (-130.0144, -52.9379)
  point P80 (-130.0144, 58.9621)
  coincident P69 P74
  coincident P68 P75
  coincident L47 P82
  coincident L51 P83
  coincident P68 P90
  parallel L58 L70
  coincident P69 P91
  dimension "d147" distance L57 L63 = 0.95 (= "side_wall_thick1")
  dimension "d148" distance L57 L61 = 1.95 (= "side_wall_thick2")
  dimension "d151" distance L57 L59 = 0.95 (= "side_wall_thick1")
  dimension "d157" distance L64 L71 = 0.05 (= "wall_clearance")
  dimension "d158" distance L58 L70 = 0.05 (= "wall_clearance")
  dimension "wall_rorner_angle" angle L46 L71 = 45
  dimension "d165" angle L52 L70 = 45 (= "wall_rorner_angle")
  dimension "d170" distance P75 P77 = 9.05
  dimension "d175" distance P74 P80 = 9.05 (= "side_wall_col_length")
extrude "Extrude1" new body sketch "wall_base" profile of L47 L48 L50 L51 L57 L58 L59 L62 L61 L60 L63 L64 blind 69.9 (= "column_height - ( 2 * wall_clearance )") from offset 0.05 (= "wall_clearance") bodies "side cover"
sketch "Sketch3" plane through (130.9644, 0, 0) normal (1, 0, 0) x axis (0, 1, 0)
  line L1 (61.9172, 5.05) -> (-67.9414, 5.05)
  line L2 (61.9172, 74.95) -> (61.9172, 5.05)
  line L3 (-67.9414, 74.95) -> (61.9172, 74.95)
  line L4 (-67.9414, 5.05) -> (-67.9414, 74.95)
  line L5 (61.9172, 74.95) -> (-67.9414, 74.95)
  line L6 (61.9172, 74.95) -> (61.9172, 5.05)
  line L7 (61.9172, 5.05) -> (-67.9414, 5.05)
  line L8 (-67.9414, 74.95) -> (-67.9414, 5.05)
  line L9 (-57.9414, 64.95) -> (51.9172, 64.95)
  line L10 (-57.9414, 15.05) -> (-57.9414, 64.95)
  line L11 (51.9172, 15.05) -> (-57.9414, 15.05)
  line L12 (51.9172, 64.95) -> (51.9172, 15.05)
  circle C1 centre (-62.995, 60) radius 1.7
  circle C2 centre (-62.995, 20) radius 1.7
  circle C3 centre (56.9879, 60) radius 1.7
  circle C4 centre (56.9879, 20) radius 1.7
hole "Hole1" HoleDepth 4 HoleDiameter 3.4 TipAngle 118
work_plane "WorkPlane1"
work_plane "WorkPlane2"
mirror_component "MirrorComponent1"
derived_instance "DerivedInstance1"
joint "Assemble3" alignAngle 0 alignOffsetX 0 alignOffsetY 0 alignOffsetZ 0
joint "Assemble4" alignAngle 0 alignOffsetX 0 alignOffsetY 0 alignOffsetZ 0
joint "Assemble5" alignAngle 90 alignOffsetX 0 alignOffsetY 0 alignOffsetZ 0
joint "Assemble6" alignAngle 0 alignOffsetX 0 alignOffsetY 0 alignOffsetZ 0
sketch "Sketch1" plane through (0, 0, 5) normal (0, 0, 1) x axis (-1, 0, 0)
  line L1 (-128.9644, -53.9879) -> (-128.9644, -59.9879)
  line L2 (-122.9644, -53.9879) -> (-128.9644, -53.9879)
  line L3 (-122.9644, -59.9879) -> (-122.9644, -53.9879)
  line L4 (-128.9644, -59.9879) -> (-122.9644, -59.9879)
  line L5 (-12.9644, 60.0121) -> (-12.9644, 66.0121)
  line L6 (-18.9644, 60.0121) -> (-12.9644, 60.0121)
  line L7 (-18.9644, 66.0121) -> (-18.9644, 60.0121)
  line L8 (-12.9644, 66.0121) -> (-18.9644, 66.0121)
  line L9 (-60.9644, -51.9879) -> (-20.9644, -51.9879)
  line L10 (-55.9644, -54.9879) -> (-60.9644, -51.9879)
  line L11 (-85.9644, -54.9879) -> (-55.9644, -54.9879)
  line L12 (-80.9644, -51.9879) -> (-85.9644, -54.9879)
  line L13 (-120.9644, -51.9879) -> (-80.9644, -51.9879)
  line L14 (-120.9644, -6.9879) -> (-120.9644, -51.9879)
  line L15 (-123.9644, -11.9879) -> (-120.9644, -6.9879)
  line L16 (-123.9644, 18.0121) -> (-123.9644, -11.9879)
  line L17 (-120.9644, 13.0121) -> (-123.9644, 18.0121)
  line L18 (-120.9644, 58.0121) -> (-120.9644, 13.0121)
  line L19 (-80.9644, 58.0121) -> (-120.9644, 58.0121)
  line L20 (-85.9644, 61.0121) -> (-80.9644, 58.0121)
  line L21 (-55.9644, 61.0121) -> (-85.9644, 61.0121)
  line L22 (-60.9644, 58.0121) -> (-55.9644, 61.0121)
  line L23 (-20.9644, 58.0121) -> (-60.9644, 58.0121)
  line L24 (-20.9644, 13.0121) -> (-20.9644, 58.0121)
  line L25 (-17.9644, 18.0121) -> (-20.9644, 13.0121)
  line L26 (-17.9644, -11.9879) -> (-17.9644, 18.0121)
  line L27 (-20.9644, -6.9879) -> (-17.9644, -11.9879)
  line L28 (-20.9644, -51.9879) -> (-20.9644, -6.9879)
  line L29 (-12.9644, -53.9879) -> (-18.9644, -53.9879)
  line L30 (-12.9644, -59.9879) -> (-12.9644, -53.9879)
  line L31 (-18.9644, -59.9879) -> (-12.9644, -59.9879)
  line L32 (-18.9644, -53.9879) -> (-18.9644, -59.9879)
  line L33 (-128.9644, 60.0121) -> (-122.9644, 60.0121)
  line L34 (-128.9644, 66.0121) -> (-128.9644, 60.0121)
  line L35 (-122.9644, 66.0121) -> (-128.9644, 66.0121)
  line L36 (-122.9644, 60.0121) -> (-122.9644, 66.0121)
  line L37 (-10.9644, -6.9879) -> (-10.9644, -61.9879)
  line L38 (-13.9644, -11.9879) -> (-10.9644, -6.9879)
  line L39 (-13.9644, 18.0121) -> (-13.9644, -11.9879)
  line L40 (-10.9644, 13.0121) -> (-13.9644, 18.0121)
  line L41 (-10.9644, 68.0121) -> (-10.9644, 13.0121)
  line L42 (-60.9644, 68.0121) -> (-10.9644, 68.0121)
  line L43 (-55.9644, 65.0121) -> (-60.9644, 68.0121)
  line L44 (-85.9644, 65.0121) -> (-55.9644, 65.0121)
  line L45 (-80.9644, 68.0121) -> (-85.9644, 65.0121)
  line L46 (-130.9644, 68.0121) -> (-80.9644, 68.0121)
  line L47 (-130.9644, 13.0121) -> (-130.9644, 68.0121)
  line L48 (-127.9644, 18.0121) -> (-130.9644, 13.0121)
  line L49 (-127.9644, -11.9879) -> (-127.9644, 18.0121)
  line L50 (-130.9644, -6.9879) -> (-127.9644, -11.9879)
  line L51 (-130.9644, -61.9879) -> (-130.9644, -6.9879)
  line L52 (-80.9644, -61.9879) -> (-130.9644, -61.9879)
  line L53 (-85.9644, -58.9879) -> (-80.9644, -61.9879)
  line L54 (-55.9644, -58.9879) -> (-85.9644, -58.9879)
  line L55 (-60.9644, -61.9879) -> (-55.9644, -58.9879)
  line L56 (-10.9644, -61.9879) -> (-60.9644, -61.9879)
  line L57 (-130.9644, -61.9879) -> (-10.9644, -61.9879)
  line L58 (-129.9644, -60.9879) -> (-130.9644, -61.9879)
  line L59 (-121.9644, -60.9879) -> (-129.9644, -60.9879)
  line L60 (-121.9644, -59.9879) -> (-121.9644, -60.9879)
  line L61 (-19.9644, -59.9879) -> (-121.9644, -59.9879)
  line L62 (-19.9644, -60.9879) -> (-19.9644, -59.9879)
  line L63 (-11.9644, -60.9879) -> (-19.9644, -60.9879)
  line L64 (-10.9644, -61.9879) -> (-11.9644, -60.9879)
  line L65 (-129.9437, -61.0379) -> (-130.8937, -61.9879)
  line L66 (-121.9144, -61.0379) -> (-129.9437, -61.0379)
  line L67 (-121.9144, -60.0379) -> (-121.9144, -61.0379)
  line L68 (-20.0144, -60.0379) -> (-121.9144, -60.0379)
  line L69 (-20.0144, -61.0379) -> (-20.0144, -60.0379)
  line L70 (-11.9851, -61.0379) -> (-20.0144, -61.0379)
  line L71 (-11.0351, -61.9879) -> (-11.9851, -61.0379)
  circle C1 centre (-24.4644, 61.5121) radius 1.7
  circle C2 centre (-123.9644, 54.5121) radius 1.7
  circle C3 centre (-117.4644, -55.4879) radius 1.7
  circle C4 centre (-17.4644, -48.4879) radius 1.7
  circle C5 centre (-24.4644, -55.4879) radius 1.7
  circle C6 centre (-123.9644, -48.4879) radius 1.7
  circle C7 centre (-117.4644, 61.5121) radius 1.7
  circle C8 centre (-17.4644, 54.5121) radius 1.7
  point P46 (-10.9644, -61.9879)
  point P74 (-10.9644, -61.9879)
  point P61 (-130.9644, -61.9879)
  point P76 (-130.9644, -61.9879)
  point P68 (-129.9644, -60.9879)
  point P77 (-129.9644, -60.9879)
  point P69 (-121.9644, -60.9879)
  point P78 (-121.9644, -60.9879)
  point P70 (-121.9644, -59.9879)
  point P79 (-121.9644, -59.9879)
  point P71 (-19.9644, -59.9879)
  point P80 (-19.9644, -59.9879)
  point P72 (-19.9644, -60.9879)
  point P81 (-19.9644, -60.9879)
  point P73 (-11.9644, -60.9879)
  point P82 (-11.9644, -60.9879)
  point P89 (-11.0351, -61.9879)
  point P90 (-130.8937, -61.9879)
  point P75 (-130.9644, -61.9879)
  coincident P46 P74
  coincident P61 P76
  coincident P68 P77
  coincident P69 P78
  coincident P70 P79
  coincident P71 P80
  coincident P72 P81
  coincident P73 P82
  coincident L56 P89
  coincident L52 P90
  dimension "column_lock_spacing" = 2
  dimension "d228" distance L57 L70 = 0.95 (= "side_wall_thick1")
  dimension "d229" distance L57 L68 = 1.95 (= "side_wall_thick2")
  dimension "d230" distance L57 L66 = 0.95 (= "side_wall_thick1")
  dimension "d231" distance P74 P75 = 120 (= "plate_height")
  dimension "d232" distance L64 L71 = 0.05 (= "wall_clearance")
  dimension "d233" distance L58 L65 = 0.05 (= "wall_clearance")
  dimension "d234" angle L57 L58 = 45 (= "wall_rorner_angle")
  dimension "d235" distance P74 L69 = 9.05 (= "side_wall_col_length")
  dimension "d244" distance P75 L67 = 9.05 (= "side_wall_col_length")
extrude "Extrude1" new body sketch "Sketch1" profile of L52 L53 L55 L56 blind 69.9 (= "column_height - ( 2 * wall_clearance )") from offset 0.05 (= "wall_clearance")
